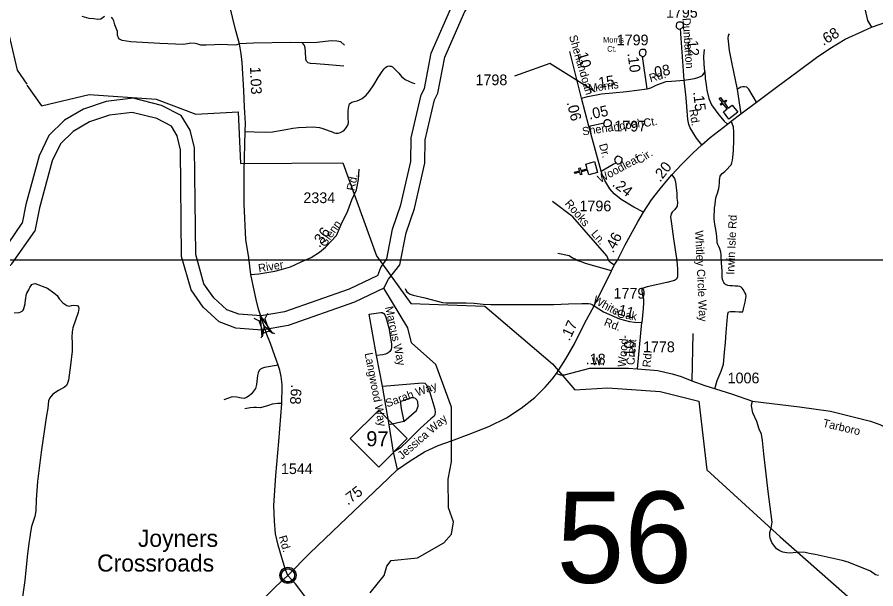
# Model space of a CAD drawing. Extents: x 2220236 to 2384410, y 720751 to 894131.
# Drawn here: x 2333123 to 2343156, y 781205 to 787885 of the extents above; entities that cross this region are included whole.
import ezdxf

# ---------------------------------------------------------------- set-up
doc = ezdxf.new("R2010")
doc.units = 0
doc.layers.add('Default', color=7, linetype='Continuous')

msp = doc.modelspace()

# ---------------------------------------------------------------- linework, layer by layer
at = {"layer": 'Default'}
for p, q in [((2340916, 787147), (2340874, 787750)), ((2339717, 786938), (2339579, 787484)), ((2340484, 787046), (2340430, 787424)), ((2341534, 787040), (2341578, 786755)), ((2339802, 786611), (2339717, 786938)), ((2339802, 786611), (2339981, 786649)), ((2335889, 784367), (2335951, 784337)), ((2336048, 784422), (2336017, 784360)), ((2336001, 784195), (2335971, 784133)), ((2336066, 784217), (2336128, 784187)), ((2341017, 784189), (2341005, 783635)), ((2337391, 783571), (2337321, 783932)), ((2337469, 783122), (2337391, 783571)), ((2337642, 783158), (2337469, 783122)), ((2337520, 782801), (2337469, 783122)), ((2337567, 782599), (2337520, 782801))]:
    msp.add_line(p, q, dxfattribs=at)
for points in [[(2329808, 816975), (2370566, 816975), (2370566, 785047), (2329808, 785047), (2329808, 816975)], [(2335853, 784876), (2335829, 785074), (2335793, 785285), (2335774, 785699), (2335777, 786091), (2335788, 786548), (2335790, 786648), (2335781, 786835), (2335772, 787028), (2335751, 787354), (2335739, 787458), (2335720, 787574), (2335676, 787740), (2335565, 788192), (2335494, 788475), (2335377, 788931), (2335352, 789038), (2335332, 789114), (2335323, 789137), (2335304, 789185), (2335263, 789258), (2335141, 789420), (2334697, 789915), (2334649, 789988)], [(2337336, 784865), (2337373, 784960), (2337442, 785062), (2337510, 785409), (2337607, 785693), (2337722, 786197), (2337728, 786473), (2337843, 786976), (2337883, 787051), (2337960, 787465), (2338212, 788039), (2338430, 788305), (2338707, 788527), (2339768, 789070), (2340543, 789418), (2340666, 789500), (2340992, 789573), (2341432, 789620), (2341905, 789745), (2342531, 789800), (2342950, 789807)], [(2337406, 784717), (2337463, 784824), (2337595, 784992), (2337669, 785366), (2337765, 785648), (2337886, 786177), (2337892, 786453), (2337998, 786918), (2338040, 786997), (2338118, 787416), (2338353, 787952), (2338546, 788188), (2338797, 788388), (2339839, 788922), (2340622, 789274), (2340731, 789346), (2341019, 789410), (2341461, 789458), (2341933, 789582), (2342540, 789636), (2342953, 789643)], [(2342993, 788470), (2342995, 788367), (2342997, 788312), (2343005, 788219), (2343017, 788115), (2343024, 788038), (2343033, 787966), (2343058, 787846), (2343105, 787767)], [(2341122, 786392), (2341220, 786479), (2341421, 786633), (2341467, 786668), (2341578, 786755), (2341761, 786891), (2341996, 787065), (2342249, 787252), (2342463, 787415), (2342617, 787519), (2342797, 787627), (2343005, 787723), (2343105, 787767), (2343319, 787841), (2343502, 787889), (2343750, 787950), (2344227, 788065), (2344748, 788196), (2344917, 788248), (2345060, 788300), (2345313, 788417)], [(2332743, 788203), (2332986, 787850), (2333123, 787266), (2333236, 787103)], [(2334145, 787894), (2334102, 787861), (2334062, 787857), (2334018, 787867), (2333965, 787868), (2333884, 787891)], [(2335720, 787574), (2335690, 787562), (2335659, 787559), (2335504, 787566), (2335427, 787562), (2335333, 787557), (2335269, 787557), (2335235, 787568), (2335204, 787579), (2335151, 787580), (2335115, 787573), (2335067, 787564), (2334791, 787576), (2334453, 787595), (2334349, 787611), (2334320, 787628), (2334307, 787645), (2334296, 787673), (2334294, 787718), (2334265, 787797), (2334251, 787841), (2334239, 787864), (2334227, 787886)], [(2340874, 787750), (2340900, 787764), (2340907, 787776), (2340909, 787800), (2340903, 787816), (2340881, 787826), (2340851, 787827), (2340839, 787823), (2340825, 787811), (2340821, 787789), (2340823, 787767), (2340840, 787753), (2340854, 787745), (2340874, 787750)], [(2341442, 787691), (2341432, 787670), (2341427, 787638), (2341444, 787496), (2341475, 787340), (2341534, 787040)], [(2336456, 787586), (2336317, 787588), (2335883, 787583), (2335720, 787574)], [(2336947, 787559), (2336903, 787596), (2336857, 787605), (2336793, 787609), (2336627, 787590), (2336456, 787586)], [(2336941, 787311), (2336762, 787328), (2336616, 787341), (2336552, 787342), (2336525, 787353), (2336505, 787372), (2336496, 787395), (2336492, 787484), (2336487, 787525), (2336479, 787555), (2336456, 787586)], [(2340430, 787424), (2340444, 787427), (2340467, 787447), (2340471, 787479), (2340465, 787499), (2340453, 787507), (2340433, 787509), (2340419, 787506), (2340403, 787498), (2340393, 787484), (2340389, 787468), (2340398, 787442), (2340412, 787432), (2340430, 787424)], [(2341157, 787251), (2341150, 787336), (2341147, 787426), (2341152, 787509)], [(2335788, 786548), (2335894, 786544), (2336021, 786540), (2336106, 786544), (2336195, 786559), (2336263, 786571), (2336343, 786588), (2336411, 786595), (2336498, 786601), (2336582, 786605), (2336618, 786601), (2336656, 786597), (2336696, 786582), (2336768, 786557), (2336802, 786544), (2336828, 786535), (2336845, 786531), (2336874, 786529), (2336900, 786537), (2336929, 786552), (2336949, 786567), (2336968, 786590), (2336987, 786622), (2336995, 786650), (2336991, 786713), (2336989, 786796), (2336997, 786842), (2337008, 786872), (2337020, 786884), (2337035, 786893), (2337061, 786901), (2337094, 786908), (2337124, 786918), (2337154, 786935), (2337202, 786973), (2337238, 787021), (2337290, 787095), (2337341, 787179), (2337386, 787251), (2337411, 787283), (2337428, 787298), (2337443, 787307), (2337464, 787315), (2337479, 787313), (2337494, 787311), (2337510, 787304), (2337538, 787273), (2337582, 787230), (2337614, 787190), (2337657, 787158), (2337709, 787133), (2337741, 787116), (2337771, 787110)], [(2339876, 787011), (2339346, 787345), (2338933, 787197)], [(2340916, 787147), (2340992, 787160), (2341037, 787168), (2341075, 787180), (2341107, 787190), (2341130, 787205), (2341147, 787228), (2341157, 787251)], [(2341157, 787251), (2341162, 787170), (2341172, 787095), (2341180, 787032), (2341205, 786935), (2341237, 786862), (2341278, 786802), (2341320, 786744), (2341385, 786671), (2341421, 786633)], [(2333236, 787092), (2333407, 786848), (2333965, 786983), (2334748, 786926), (2335212, 786750), (2335707, 786780), (2335732, 786176), (2336928, 786183), (2337321, 785094), (2337723, 784537), (2338587, 784509), (2339379, 783833), (2339637, 783530), (2340026, 783555), (2340637, 783510), (2341088, 783396), (2341182, 782595), (2342039, 781812), (2342989, 780974), (2343263, 780727)], [(2340484, 787046), (2340525, 787061), (2340590, 787092), (2340651, 787115), (2340707, 787133), (2340768, 787137), (2340916, 787147)], [(2341122, 786392), (2341061, 786470), (2340986, 786593), (2340971, 786631), (2340960, 786691), (2340941, 786943), (2340916, 787147)], [(2341761, 786891), (2341670, 787045), (2341648, 787065), (2341620, 787069), (2341600, 787069), (2341580, 787066), (2341560, 787056), (2341534, 787040)], [(2339717, 786938), (2339792, 786959), (2339951, 786988), (2340081, 787000), (2340241, 787017), (2340484, 787046)], [(2337336, 784865), (2337001, 784705), (2336248, 784442), (2335974, 784393), (2335712, 784413), (2335571, 784465), (2335420, 784605), (2335306, 784769), (2335209, 785112), (2335194, 786357), (2335145, 786563), (2335041, 786735), (2334811, 786853), (2334479, 786939), (2334164, 786901), (2333899, 786810), (2333676, 786681), (2333493, 786502), (2333379, 786265), (2333224, 785694), (2333181, 785477)], [(2337406, 784717), (2337064, 784554), (2336290, 784282), (2335982, 784228), (2335677, 784251), (2335483, 784323), (2335296, 784497), (2335156, 784698), (2335045, 785088), (2335030, 786336), (2334991, 786500), (2334925, 786610), (2334753, 786699), (2334468, 786772), (2334201, 786740), (2333967, 786660), (2333776, 786549), (2333629, 786405), (2333533, 786207), (2333384, 785657), (2333331, 785385)], [(2339981, 786649), (2339989, 786678), (2340009, 786688), (2340027, 786690), (2340045, 786682), (2340055, 786672), (2340065, 786656), (2340063, 786634), (2340054, 786614), (2340034, 786606), (2340014, 786602), (2339992, 786607), (2339980, 786621), (2339977, 786637), (2339981, 786649)], [(2341274, 783541), (2341303, 783638), (2341347, 783750), (2341374, 783831), (2341379, 783871), (2341388, 783970), (2341398, 784079), (2341406, 784201), (2341420, 784341), (2341427, 784418), (2341435, 784443), (2341458, 784446), (2341486, 784446), (2341511, 784447), (2341554, 784443), (2341603, 784442), (2341611, 784477), (2341628, 784555), (2341637, 784601), (2341639, 784626), (2341636, 784646), (2341626, 784667), (2341606, 784702), (2341593, 784719), (2341582, 784729), (2341566, 784736), (2341544, 784741), (2341514, 784742), (2341481, 784744), (2341451, 784746), (2341425, 784751), (2341401, 784759), (2341387, 784773), (2341379, 784784), (2341371, 784799), (2341364, 784821), (2341362, 784853), (2341359, 784922), (2341351, 785012), (2341348, 785108), (2341343, 785140), (2341332, 785178), (2341320, 785204), (2341309, 785227), (2341303, 785246), (2341302, 785269), (2341295, 785355), (2341283, 785422), (2341270, 785490), (2341266, 785534), (2341266, 785575), (2341269, 785616), (2341271, 785657), (2341278, 785697), (2341284, 785748), (2341292, 785784), (2341305, 785827), (2341323, 785884), (2341327, 785909), (2341328, 785948), (2341328, 785976), (2341332, 786002), (2341338, 786026), (2341345, 786039), (2341359, 786057), (2341390, 786081), (2341419, 786110), (2341451, 786142), (2341466, 786160), (2341475, 786182), (2341481, 786213), (2341485, 786246), (2341493, 786327), (2341497, 786448), (2341497, 786545), (2341491, 786599), (2341477, 786643), (2341467, 786668)], [(2340440, 785607), (2340328, 785665), (2340181, 785754), (2340098, 785819), (2340049, 785880), (2340036, 785900), (2340012, 785936), (2339988, 785975), (2339965, 786022), (2339946, 786086), (2339802, 786611)], [(2340440, 785607), (2340536, 785750), (2340635, 785877), (2340725, 785989), (2340774, 786042), (2340884, 786164), (2341016, 786297), (2341122, 786392)], [(2340121, 786183), (2340137, 786169), (2340153, 786170), (2340177, 786180), (2340187, 786198), (2340192, 786218), (2340190, 786232), (2340184, 786242), (2340158, 786256), (2340138, 786259), (2340122, 786247), (2340112, 786237), (2340104, 786213), (2340109, 786195), (2340121, 786183)], [(2339946, 786086), (2340085, 786169), (2340121, 786183)], [(2335853, 784876), (2335947, 784886), (2336133, 784916), (2336207, 784938), (2336318, 784968), (2336443, 785026), (2336560, 785076), (2336654, 785140), (2336724, 785196), (2336853, 785334), (2336910, 785461), (2336986, 785622), (2337033, 785749), (2337087, 785866), (2337113, 785986), (2337120, 786109)], [(2340774, 786042), (2340803, 785999), (2340814, 785961), (2340831, 785825), (2340832, 785771), (2340838, 785722), (2340833, 785678), (2340809, 785636), (2340778, 785607), (2340766, 785587), (2340756, 785553), (2340768, 785471), (2340791, 785295), (2340827, 785065), (2340833, 784997), (2340838, 784936), (2340840, 784898), (2340838, 784849), (2340826, 784825), (2340804, 784809), (2340713, 784784), (2340485, 784732), (2340447, 784723), (2340427, 784713), (2340421, 784701), (2340421, 784682), (2340431, 784636), (2340442, 784594), (2340442, 784548), (2340437, 784481), (2340422, 784316)], [(2340098, 784987), (2340039, 785028), (2340027, 785056), (2340023, 785068), (2340012, 785095), (2339616, 785551), (2339377, 785729)], [(2339864, 784513), (2340069, 784920), (2340098, 784987), (2340138, 785047), (2340228, 785226), (2340373, 785493), (2340440, 785607)], [(2330163, 784085), (2330733, 784611), (2330993, 784732), (2331482, 784833), (2332573, 784910), (2332830, 785019), (2332936, 785114), (2333181, 785477)], [(2330270, 783969), (2330825, 784473), (2331045, 784575), (2331504, 784670), (2332612, 784748), (2332919, 784879), (2333059, 785004), (2333331, 785385)], [(2340069, 784920), (2339764, 785008), (2339716, 785026), (2339675, 785038), (2339659, 785047), (2339643, 785055), (2339611, 785069), (2339573, 785094), (2339439, 785124)], [(2336022, 784235), (2335990, 784334), (2335943, 784474), (2335916, 784585), (2335898, 784676), (2335853, 784876)], [(2333087, 784429), (2333145, 784435), (2333167, 784440), (2333183, 784448), (2333195, 784460), (2333201, 784472), (2333200, 784482), (2333218, 784536), (2333219, 784584), (2333223, 784598), (2333229, 784636), (2333237, 784660), (2333258, 784698), (2333263, 784711), (2333272, 784724), (2333296, 784760), (2333312, 784768), (2333332, 784772), (2333477, 784718), (2333551, 784665), (2333590, 784633), (2333614, 784595), (2333655, 784548), (2333705, 784515), (2333729, 784509), (2333759, 784517), (2333787, 784520), (2333819, 784514), (2333833, 784510), (2333839, 784498), (2333843, 784480), (2333836, 784434), (2333772, 784253), (2333765, 784207), (2333761, 784147), (2333764, 784079), (2333765, 783981), (2333745, 783817), (2333722, 783641), (2333712, 783609), (2333698, 783579), (2333678, 783561), (2333607, 783522), (2333541, 783481), (2333504, 783437), (2333488, 783402), (2333482, 783316), (2333463, 783206), (2333402, 782803), (2333362, 782459), (2333346, 782247), (2333342, 782117), (2333331, 782051), (2333290, 781931), (2333278, 781865), (2333270, 781807), (2333260, 781739), (2333238, 781580)], [(2337248, 781159), (2337413, 781360), (2337444, 781469), (2337494, 781537), (2337802, 781566), (2338108, 781743), (2338198, 781845), (2338221, 781987), (2338161, 782152), (2338157, 782486), (2338196, 782688), (2338197, 783328), (2338016, 783826), (2337730, 784080), (2337686, 784256), (2337406, 784717)], [(2337657, 784714), (2337663, 784693), (2337674, 784677), (2337691, 784662), (2337716, 784649), (2337749, 784637), (2337888, 784604), (2338092, 784551), (2338135, 784547), (2338208, 784545), (2338368, 784545), (2338464, 784542), (2338569, 784532), (2338659, 784528), (2338823, 784526), (2338985, 784527), (2339153, 784528), (2339392, 784529), (2339565, 784534), (2339722, 784538), (2339797, 784538), (2339822, 784536), (2339843, 784529), (2339864, 784513)], [(2339424, 783720), (2339534, 783894), (2339636, 784067), (2339753, 784306), (2339864, 784513)], [(2339864, 784513), (2339974, 784443), (2340159, 784358), (2340279, 784330), (2340335, 784321), (2340422, 784316)], [(2337321, 783932), (2337237, 784413), (2337373, 784433), (2337387, 784432), (2337407, 784423), (2337419, 784407), (2337431, 784381), (2337467, 784256), (2337490, 784114), (2337497, 784064), (2337496, 784030), (2337492, 784000), (2337478, 783976), (2337458, 783962), (2337425, 783946), (2337397, 783939), (2337321, 783932)], [(2340372, 783775), (2340422, 784316)], [(2336287, 781362), (2336253, 781439), (2336211, 781584), (2336172, 781715), (2336142, 781847), (2336128, 781995), (2336121, 782180), (2336144, 782529), (2336181, 782927), (2336216, 783370), (2336216, 783425), (2336221, 783520), (2336220, 783594), (2336207, 783684), (2336192, 783758), (2336173, 783818), (2336135, 783928), (2336084, 784072), (2336041, 784176), (2336022, 784235)], [(2336173, 783818), (2336013, 783791), (2335989, 783782), (2335967, 783770), (2335951, 783754), (2335938, 783730), (2335931, 783696), (2335919, 783591), (2335906, 783545), (2335861, 783483), (2335835, 783460), (2335804, 783441), (2335774, 783430), (2335744, 783431), (2335689, 783446), (2335637, 783447), (2335536, 783413)], [(2339424, 783720), (2339469, 783704), (2339518, 783706), (2339813, 783782), (2340266, 783784), (2340372, 783775)], [(2340372, 783775), (2340608, 783754), (2340689, 783735), (2340776, 783716), (2340883, 783685), (2341005, 783635), (2341156, 783582), (2341469, 783482), (2341714, 783399), (2342262, 783332), (2342625, 783279), (2342922, 783207), (2343094, 783163), (2343203, 783124), (2343264, 783095), (2343331, 783060), (2343413, 783015), (2343554, 782925), (2343671, 782842), (2343797, 782756), (2343955, 782634), (2344159, 782498), (2344430, 782354), (2344623, 782256)], [(2336287, 781362), (2336544, 781621), (2336892, 781957), (2337457, 782495), (2337567, 782599), (2337713, 782701), (2337884, 782807), (2338041, 782879), (2338196, 782935), (2338404, 783010), (2338635, 783102), (2338841, 783202), (2339012, 783314), (2339172, 783440), (2339292, 783562), (2339374, 783656), (2339424, 783720)], [(2337391, 783571), (2337860, 783613), (2337887, 783607), (2337907, 783587), (2337946, 783498), (2338002, 783303), (2338007, 783265), (2338003, 783241), (2337995, 783223), (2337957, 783192), (2337836, 783082), (2337691, 782937), (2337600, 782854), (2337520, 782801)], [(2336216, 783370), (2336170, 783371), (2336104, 783364), (2336058, 783345), (2335965, 783320), (2335921, 783322), (2335887, 783325), (2335845, 783321), (2335783, 783308)], [(2337642, 783158), (2337790, 783288), (2337810, 783340), (2337803, 783388), (2337791, 783414), (2337777, 783430), (2337757, 783438), (2337725, 783435), (2337619, 783398), (2337607, 783392), (2337601, 783384), (2337601, 783372), (2337608, 783310), (2337642, 783158)], [(2343186, 781360), (2343150, 781369), (2343095, 781409), (2342834, 781515), (2342764, 781537), (2342447, 781605), (2342375, 781618), (2342329, 781631), (2342257, 781634), (2342157, 781621), (2342117, 781625), (2342071, 781634), (2342033, 781650), (2341996, 781671), (2341941, 781745), (2341921, 781796), (2341919, 781824), (2341918, 781862), (2341934, 781913), (2341945, 781983), (2341898, 782340), (2341847, 782783), (2341833, 782937), (2341818, 783011), (2341794, 783072), (2341765, 783160), (2341719, 783260), (2341702, 783343), (2341706, 783371), (2341714, 783399)], [(2333238, 781580), (2333211, 781303), (2333177, 781057), (2333163, 780895)], [(2334887, 779938), (2335010, 780077), (2335118, 780195), (2335335, 780419), (2335589, 780675), (2335863, 780947), (2336144, 781231), (2336287, 781362)], [(2337127, 780401), (2336965, 780531), (2336850, 780643), (2336752, 780754), (2336530, 781058), (2336376, 781261), (2336287, 781362)]]:
    msp.add_lwpolyline(points, dxfattribs=at)
for points in [[(2341374, 786779), (2341419, 786814), (2341373, 786874), (2341347, 786855), (2341338, 786868), (2341363, 786887), (2341327, 786935), (2341340, 786945), (2341376, 786897), (2341402, 786916), (2341411, 786903), (2341386, 786884), (2341432, 786823), (2341478, 786858), (2341542, 786773), (2341438, 786694)], [(2339801, 786043), (2339786, 786098), (2339712, 786078), (2339721, 786047), (2339705, 786043), (2339697, 786074), (2339639, 786058), (2339635, 786074), (2339693, 786089), (2339684, 786120), (2339700, 786124), (2339708, 786094), (2339782, 786114), (2339767, 786169), (2339869, 786197), (2339904, 786071)], [(2336017, 784360), (2336067, 784217), (2336000, 784194), (2335951, 784337)], [(2335987, 784148), (2335967, 784391), (2336106, 784190), (2336008, 784276)], [(2337015, 782961), (2337348, 783294), (2337681, 782961), (2337348, 782628)], [(2336210, 781374), (2336211, 781380), (2336212, 781387), (2336215, 781394), (2336218, 781400), (2336222, 781405), (2336225, 781410), (2336229, 781415), (2336234, 781419), (2336239, 781424), (2336245, 781428), (2336250, 781430), (2336255, 781433), (2336260, 781435), (2336266, 781437), (2336270, 781438), (2336275, 781439), (2336279, 781440), (2336286, 781440), (2336290, 781440), (2336296, 781440), (2336301, 781439), (2336305, 781438), (2336310, 781436), (2336316, 781434), (2336322, 781432), (2336329, 781428), (2336334, 781425), (2336339, 781420), (2336342, 781417), (2336346, 781413), (2336350, 781408), (2336353, 781404), (2336356, 781399), (2336359, 781394), (2336361, 781389), (2336362, 781383), (2336364, 781379), (2336365, 781373), (2336365, 781368), (2336366, 781362), (2336365, 781356), (2336365, 781351), (2336364, 781345), (2336362, 781339), (2336360, 781333), (2336358, 781328), (2336355, 781322), (2336352, 781317), (2336348, 781312), (2336344, 781307), (2336339, 781302), (2336334, 781298), (2336329, 781295), (2336324, 781292), (2336317, 781289), (2336310, 781286), (2336304, 781285), (2336298, 781284), (2336293, 781283), (2336289, 781283), (2336283, 781283), (2336279, 781283), (2336273, 781284), (2336267, 781285), (2336263, 781287), (2336258, 781289), (2336253, 781291), (2336249, 781293), (2336242, 781297), (2336237, 781301), (2336232, 781306), (2336227, 781310), (2336224, 781314), (2336221, 781319), (2336217, 781326), (2336215, 781329), (2336214, 781333), (2336211, 781341), (2336210, 781348), (2336209, 781354), (2336209, 781360), (2336209, 781365), (2336209, 781371)]]:
    msp.add_lwpolyline(points, close=True, dxfattribs=at)
for radius in [94.3, 76.7]:
    msp.add_circle((2336287, 781362), radius, dxfattribs=at)

# ---------------------------------------------------------------- texts
for s, height, p in [('1795', 125, (2340703, 787879)), ('Morris', 65.6, (2339968, 787588)), ('1799', 125, (2340128, 787556)), ('  Ct.', 65.6, (2339968, 787482)), ('1798', 125, (2338478, 787090)), ('1797', 125, (2340101, 786549)), ('2334', 125, (2336467, 785712)), ('1796', 125, (2339693, 785616)), ('1779', 125, (2340091, 784596)), ('1778', 125, (2340435, 783970)), ('1006', 125, (2341424, 783606)), ('97', 175, (2337202, 782871)), ('1544', 125, (2336205, 782546)), ('56', 1066.3, (2339424, 781275)), ('Joyners', 200, (2334534, 781695)), ('Crossroads', 200, (2334057, 781406))]:
    msp.add_text(s, height=height, dxfattribs=at).set_placement(p)
for s, height, rotation, p in [('Dunbarton', 95, 273.9849, (2340896, 787873)), ('.68', 125, 30.9586, (2342542, 787547)), ('Shenandoah', 95, 286.1869, (2339570, 787661)), ('.12', 125, 273.9849, (2340952, 787658)), ('.10', 125, 286.1869, (2339652, 787502)), ('.10', 125, 277.8554, (2340253, 787462)), ('1.03', 125, 272.6009, (2335843, 787304)), ('Rd.', 95, 15.9449, (2340522, 787124)), ('.08', 125, 10.6249, (2340534, 787171)), ('.15', 125, 8.2587, (2339877, 787050)), ('Morris', 95, 8.2587, (2339807, 787006)), ('.15', 125, 276.9037, (2341020, 787011)), ('.06', 125, 284.0001, (2339543, 786887)), ('.05', 125, 11.7331, (2339811, 786688)), ('Rd.', 95, 280.0192, (2340974, 786802)), ('Shenandoah', 95, 8.3372, (2339732, 786502)), ('Ct.', 95, 9.4667, (2340448, 786600)), ('Dr.', 95, 285.2188, (2339920, 786395)), ('Woodleaf', 95, 28.3216, (2339935, 785945)), ('Cir.', 95, 33.5404, (2340394, 786165)), ('.20', 125, 51.8001, (2340635, 785951)), ('Rd.', 95, 78.2378, (2337063, 785850)), ('.24', 125, 322.4392, (2340068, 785919)), ('Rooks', 95, 310.6629, (2339516, 785703)), ('Irwin Isle Rd', 95, 87.4451, (2341501, 784874)), ('Glenn', 95, 54.8803, (2336721, 785192)), ('.36', 125, 54.8803, (2336656, 785184)), ('Ln.', 95, 310.6003, (2339823, 785350)), ('.46', 125, 62.3436, (2340087, 785122)), ('Whitley Circle Way', 95, 272.6196, (2341044, 785390)), ('River', 95, 9.095, (2335947, 784903)), ('White', 95, 331.5871, (2339841, 784551)), ('Marcus Way', 95, 282.1948, (2337422, 784496)), ('.11', 125, 345.5727, (2340089, 784422)), ('Oak', 95, 350.181, (2340126, 784379)), ('.17', 125, 64.7858, (2339576, 784093)), ('Rd.', 95, 338.8656, (2339972, 784286)), ('Wood-', 95, 85.2722, (2340234, 783794)), ('.10', 125, 89.0294, (2340335, 783871)), ('Crest', 95, 85.2722, (2340334, 783816)), ('Langwood Way', 95, 280.7793, (2337183, 783956)), ('.18', 125, 359.1091, (2339765, 783830)), ('Rd.', 95, 85.2722, (2340523, 783790)), ('W.', 95, 0.0819, (2339837, 783815)), ('.68', 125, 266.2243, (2336325, 783595)), ('Sarah Way', 95, 20.0649, (2337447, 783324)), ('Jessica Way', 95, 40.9917, (2337619, 782712)), ('Tarboro', 95, 346.6797, (2342529, 783100)), ('.75', 125, 37.3559, (2336987, 782176)), ('Rd.', 95, 286.771, (2336177, 781813))]:
    msp.add_text(s, height=height, rotation=rotation, dxfattribs=at).set_placement(p)

doc.saveas('drawing.dxf')
